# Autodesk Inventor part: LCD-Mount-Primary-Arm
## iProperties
Company: Autodesk, Inc.
Shininess: 64.0
Length Units: 11269
Angle Units: 11279
Time Units: 11290
Mass Units: 11283
Length Display Precision: 3
Angle Display Precision: 2
Compacted: True
Part Number: LCD-Mount-Primary-Arm
Document SubType Name: Modeling
Created: 2003-12
Catalog Web Link: www.autodesk.com
Vendor: Autodesk, Inc.
Designer: Administrator
Manufacturer: Standard
Standards Organization: Custom
Density: 1 g/cm^3
Density: 0.0
Volumn: 0.0
Area: 0.0
PropertySet Name: Model Information
Control State: 0
Master: False
Checked Out: False
Author: Administrator
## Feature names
1. Extrusion1
2. Shell1
3. Fillet1
4. Hole2
